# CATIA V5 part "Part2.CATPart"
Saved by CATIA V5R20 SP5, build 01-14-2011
Part number: Part2
Bounding box of the stored display mesh (mm): x -100 to 100, y -99.819 to 99.819, z 0 to 10
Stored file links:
  C:\Documents and Settings\Student\桌面\考试\Part2.CATPart
  E:\xhd\考试\Part1.CATPart
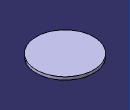
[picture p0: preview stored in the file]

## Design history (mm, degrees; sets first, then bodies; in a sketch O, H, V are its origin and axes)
Body1 (main body)
  Set1
    Sketch1 on zx-plane, origin (0, 0, 0), H (-1, 0, 0), V (0, 0, 1)
      point P1 (0, 10)
      line L1 (0, 10) -> (100, 10)
      line L2 (100, 10) -> (100, 0)
      line L3 (100, 0) -> (0, 0)
      line L4 (0, 0) -> (0, 10)
      coincidence: P1 V
      horizontal: L1 H, L3 H
      vertical: L2 V, L4 V
  Shaft1: profile Sketch1, axis Sketch1.L4, angle 360
  Sketch2 on face, origin (0, 0, -46), H (1, 0, 0), V (0, -1, 0)
  Pad1: profile Sketch2, direction (0, 0, 1), length 10, deactivated
  Sketch3 on face, origin (0, 0, -46), H (1, 0, 0), V (0, -1, 0)
    circle A1 centre (66.5893, 34.509) radius 15
    point P1 (66.5893, 34.509)
    circle A2 centre (61.8186, -40.3391) radius 15
    point P2 (61.8186, -40.3391)
    circle A3 centre (-4.1404, -76.0379) radius 15
    point P3 (-4.1404, -76.0379)
    circle A4 centre (-68.9033, -38.2123) radius 15
    point P4 (-68.9033, -38.2123)
    circle A5 centre (1.1854, 71.215) radius 15
    point P5 (1.1854, 71.215)
    circle A6 centre (-65.4039, 36.706) radius 15
    point P6 (-65.4039, 36.706)
    distance O P1 = 75
    distance P1 A1 = 15
    distance P2 A2 = 15
    distance P2 P1 = 75
    distance P3 A3 = 15
    distance P2 P3 = 75
    distance P4 A4 = 15
    distance P4 P3 = 75
    distance P5 P1 = 75
    distance P5 A5 = 15
    distance P6 A6 = 15
    distance P6 O = 75
    distance P5 P6 = 75
    distance P4 P6 = 75
  Pad2: profile Sketch3, direction (0, 0, 1), length 10, deactivated
  Point1: stored without definition
  Point2: stored without definition
  Sketch4 on face of Shaft1 from Sketch1.L1, origin (0, 0, 10), H (1, 0, 0), V (0, 1, 0)
    circle A1 centre (16.6284, 73.1334) radius 15
    point P1 (16.6284, 73.1334)
    circle A2 centre (-16.6284, -73.1334) radius 15.951
    point P2 (-16.6284, -73.1334)
    reference projected point E1 (0, 0) from vertex of Point1
    reference projected point E2 (0, 0) from vertex of Point2
    distance P2 P1 = 150
    distance P1 E1 = 75
    distance P2 E2 = 75
  Pad3: profile Sketch4, direction (0, 0, 1), length 10
Current feature: Pad2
